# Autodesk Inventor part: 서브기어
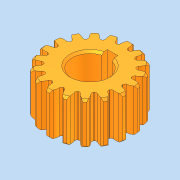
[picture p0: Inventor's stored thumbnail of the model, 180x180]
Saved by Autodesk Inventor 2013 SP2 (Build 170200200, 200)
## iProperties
Company: 한국ATC센터
Created: 2014-12
Part Number: 서브기어
Document SubType Name: Modeling
Designer: KYOUNG IL JANG
Density: 1 g/cm^3
Mass: 15.166 g
Surface Area: 69.6172 cm^2
Volume: 15.166 cm^3
Material: 일반
Author: KYOUNG IL JANG
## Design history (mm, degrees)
sketch "스케치1"
  geometry: C1 r 15.5 at (0, 0); A1 r 1.155 centre (-2.906, 16.386) between (-2.542, 15.29) and (-1.751, 16.378); A2 r 5.602 centre (3.849, 16.522) between (-1.326, 18.666) and (-1.751, 16.378); A3 r 9.354 centre (7.378, 15.24) between (-0.682, 19.988) and (-1.326, 18.666); A4 r 1.155 centre (2.906, 16.386) between (1.751, 16.378) and (2.542, 15.29); A5 r 5.602 centre (-3.849, 16.522) between (1.751, 16.378) and (1.326, 18.666); A6 r 9.354 centre (-7.378, 15.24) between (1.326, 18.666) and (0.682, 19.988); A7 r 20 centre (0, 0) between (0.682, 19.988) and (-0.682, 19.988); A8 r 15.5 centre (0, 0) between (2.542, 15.29) and (-2.542, 15.29); 1 further point
  constraints: 16 point on circle, 9 centre point, 2 coincident
extrude "돌출1" new body sketch "스케치1" stored distance "d0" = 20; taper "d1" = 0 deg
extrude "돌출2" join sketch "스케치1" stored distance "d2" = 20; taper "d3" = 0 deg
chamfer "모따기1" distance "d4" = 1; stored, may be unused: second distance "d5" = 2, angle "d6" = 45 deg
hole "구멍1" diameter "d12" = 17; stored, may be unused: countersink angle "d16" = 90 deg, drill point angle "d18" = 118 deg; dims "d10" = 10, "d11" = 10, "d13" = 6, "d14" = 4, "d15" = 2, "d17" = 8
sketch "스케치2"
  geometry: L1 (-2.5, 8.124)-(-2.5, 10.8); L2 (-2.5, 10.8)-(2.5, 10.8); L3 (2.5, 10.8)-(2.5, 8.124); A1 r 8.5 centre (0, 0) between (-2.5, 8.124) and (2.5, 8.124) reference; 1 further point
  constraints: 6 end point, 2 parallel, 2 point on circle, 1 horizontal, 1 vertical
  dimensions: "d22" = 5 distance of L1.end L2.end; "d23" = 2.3 distance edge to line of A1 L2
extrude "돌출3" cut sketch "스케치2" stored distance "d24" = 20; taper "d25" = 0 deg
chamfer "모따기2" distance "d19" = 1; stored, may be unused: second distance "d20" = 2, angle "d21" = 45 deg
node "솔리드1"
pattern_circular "원형 패턴1" dims angle "d8" = 360 deg
